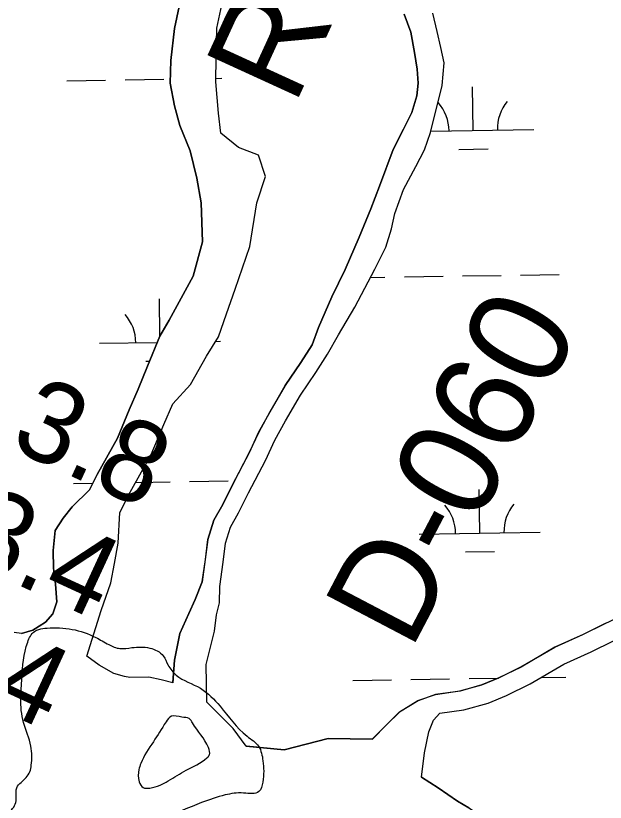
# Model space of a CAD drawing. Extents: x 3855477 to 3893699, y 299188 to 325115.
# Drawn here: x 3867459 to 3867946, y 314439 to 315089 of the extents above; entities that cross this region are included whole.
import ezdxf

# ---------------------------------------------------------------- set-up
doc = ezdxf.new("R2010")
doc.units = 0
for name, color, linetype in [('V-RIVR-EDGE', 7, 'Continuous'), ('V-RIVR-RANG', 7, 'Continuous'), ('V-RIVR-RANG-IDEN', 7, 'Continuous'), ('V-TOPO-SHOR', 7, 'Continuous'), ('V-WETL-SWMP', 7, 'Continuous')]:
    doc.layers.add(name, color=color, linetype=linetype)

msp = doc.modelspace()

# ---------------------------------------------------------------- linework, layer by layer
at = {"layer": 'V-RIVR-EDGE'}
for points in [[(3862579.14, 316706.58), (3862618.94, 316682.57), (3862652.77, 316666.14), (3862683.04, 316656.5), (3862696.18, 316652.88), (3862701.35, 316646.89), (3862715.28, 316640.08), (3862730.01, 316634.47), (3862738.78, 316633.65), (3862748.32, 316626.05), (3862763.45, 316620.43), (3862771.01, 316614.84), (3862792.51, 316606.02), (3862806.84, 316598.81), (3862817.99, 316594.4), (3862834.31, 316586.78), (3862853.02, 316578.37), (3862861.77, 316570.77), (3862880.08, 316564.75), (3862890.05, 316564.73), (3862900.01, 316564.3), (3862907.58, 316561.49), (3862923.9, 316554.68), (3862944.6, 316544.66), (3862975.64, 316529.04), (3863008.68, 316511.03), (3863036.93, 316493.42), (3863051.26, 316484.22), (3863059.61, 316479.82), (3863073.14, 316469.42), (3863078.7, 316461.84), (3863091.04, 316455.43), (3863113.73, 316446.6), (3863137.23, 316440.57), (3863166.3, 316430.53), (3863183.42, 316425.71), (3863207.7, 316412.1), (3863228, 316399.69), (3863238.35, 316395.68), (3863252.68, 316390.47), (3863259.44, 316385.27), (3863266.6, 316378.08), (3863269.37, 316370.9), (3863279.32, 316363.3), (3863294.44, 316355.69), (3863309.17, 316346.89), (3863343, 316331.26), (3863355.34, 316322.06), (3863380.4, 316304.47), (3863423.37, 316277.26), (3863452.02, 316258.46), (3863472.72, 316247.65), (3863532.42, 316214.82), (3863576.2, 316192.79), (3863612.02, 316173.97), (3863662.97, 316147.94), (3863701.98, 316129.91), (3863762.09, 316101.46), (3863803.49, 316080.64), (3863847.67, 316056.62), (3863876.33, 316044.19), (3863896.63, 316031.79), (3863917.72, 316020.58), (3863971.85, 315991.35), (3864020.81, 315966.12), (3864054.23, 315946.51), (3864091.65, 315926.89), (3864114.73, 315913.68), (3864131.85, 315906.86), (3864146.97, 315897.66), (3864174.04, 315883.64), (3864183.18, 315874.06), (3864194.33, 315870.44), (3864207.47, 315866.82), (3864224.19, 315858.81), (3864239.32, 315850.4), (3864262.4, 315839.98), (3864273.56, 315837.17), (3864288.68, 315830.35), (3864303.82, 315827.93), (3864315.37, 315825.11), (3864338.47, 315817.08), (3864360.77, 315810.65), (3864391.41, 315792.24), (3864418.87, 315776.23), (3864435.97, 315762.24), (3864459.04, 315741.86), (3864510.37, 315709.85), (3864535.44, 315695.84), (3864548.97, 315685.44), (3864561.3, 315675.85), (3864568.85, 315666.66), (3864582.37, 315656.66), (3864595.1, 315647.07), (3864600.67, 315641.08), (3864607.02, 315633.09), (3864612.59, 315626.3), (3864620.15, 315622.69), (3864637.27, 315615.88), (3864659.57, 315609.05), (3864678.28, 315601.03), (3864697.4, 315595.4), (3864745.56, 315571.77), (3864769.85, 315563.74), (3864787.37, 315555.73), (3864811.24, 315540.52), (3864821.2, 315537.71), (3864833.16, 315537.68), (3864842.32, 315536.46), (3864849.48, 315531.26), (3864857.43, 315522.87), (3864872.16, 315516.86), (3864908, 315506.01), (3864925.13, 315500.39), (3864937.87, 315498.76), (3864948.62, 315491.56), (3864956.98, 315489.55), (3864964.15, 315487.54), (3865017.51, 315468.28), (3865068.47, 315449.82), (3865096.34, 315439.39), (3865128.59, 315424.96), (3865154.87, 315414.93), (3865175.96, 315401.73), (3865212.19, 315385.7), (3865243.63, 315368.48), (3865263.13, 315356.48), (3865277.85, 315348.07), (3865296.96, 315338.06), (3865316.47, 315331.24), (3865337.16, 315318.04), (3865369.39, 315298.43), (3865405.2, 315275.22), (3865431.87, 315259.61), (3865448.19, 315254), (3865473.66, 315238.39), (3865499.13, 315224.78), (3865515.06, 315217.96), (3865531.77, 315209.15), (3865549.68, 315199.54), (3865571.18, 315191.52), (3865609, 315173.09), (3865653.97, 315145.48), (3865693.76, 315123.07), (3865732.77, 315101.85), (3865776.94, 315077.43), (3865798.43, 315063.82), (3865826.69, 315046.62), (3865853.35, 315032.6), (3865883.2, 315017.39), (3865895.15, 315011.38), (3865904.29, 315003.78), (3865913.04, 314994.59), (3865919.8, 314990.19), (3865927.77, 314987.38), (3865939.71, 314983.37), (3865950.47, 314980.55), (3865961.62, 314976.54), (3865977.53, 314967.34), (3866028.88, 314942.9), (3866056.75, 314928.48), (3866076.64, 314915.28), (3866096.53, 314901.68), (3866120.41, 314888.47), (3866143.9, 314878.05), (3866161.41, 314867.25), (3866178.14, 314862.82), (3866201.24, 314856.79), (3866223.14, 314850.36), (3866245.83, 314837.55), (3866263.73, 314827.14), (3866282.84, 314818.72), (3866292.41, 314818.7), (3866300.78, 314818.28), (3866309.94, 314816.27), (3866326.66, 314808.65), (3866348.53, 314791.06), (3866360.08, 314786.25), (3866377.59, 314778.64), (3866387.55, 314775.02), (3866394.31, 314767.44), (3866401.87, 314762.24), (3866413.81, 314757.03), (3866423.36, 314751.42), (3866432.12, 314749.81), (3866437.69, 314746.21), (3866445.65, 314739.41), (3866454.4, 314732.22), (3866485.45, 314718.99), (3866510.53, 314708.56), (3866533.21, 314691.37), (3866541.97, 314691.35), (3866549.94, 314690.93), (3866556.31, 314686.53), (3866561.87, 314678.55), (3866573.8, 314670.15), (3866598.9, 314663.71), (3866631.14, 314649.28), (3866660.61, 314640.44), (3866694.86, 314628.4), (3866748.2, 314604.36), (3866780.45, 314591.52), (3866811.1, 314575.51), (3866846.93, 314561.47), (3866895.5, 314539.03), (3866932.13, 314524.59), (3866954.81, 314513.38), (3866988.26, 314500.54), (3867018.51, 314486.52), (3867041.2, 314475.3), (3867068.66, 314458.5), (3867097.31, 314440.09), (3867123.99, 314432.46), (3867147.11, 314433.2), (3867169.41, 314427.96), (3867197.28, 314417.13), (3867215.2, 314410.71), (3867238.69, 314401.49), (3867251.43, 314396.27), (3867258.61, 314395.86), (3867271.36, 314397.42), (3867288.1, 314397.78), (3867302.45, 314396.15), (3867345.46, 314385.28), (3867427.5, 314359.57), (3867438.25, 314357.95), (3867445.03, 314357.93), (3867453.42, 314369.47), (3867458.24, 314381.41), (3867462.26, 314395.75), (3867462.28, 314404.12), (3867460.7, 314411.7), (3867457.12, 314414.1), (3867450.75, 314416.11), (3867442.78, 314416.52), (3867438.8, 314420.12), (3867443.19, 314422.1), (3867451.58, 314428.06), (3867458.77, 314437.21), (3867459.58, 314442.79), (3867460, 314450.75), (3867463.6, 314455.13), (3867470.8, 314463.88), (3867472, 314469.46), (3867472.42, 314477.03), (3867471.64, 314485), (3867465.71, 314504.54), (3867463.75, 314514.51), (3867463.37, 314524.48), (3867464.21, 314541.21), (3867469.07, 314571.09), (3867474.67, 314579.84), (3867478.26, 314581.43), (3867485.04, 314582.61), (3867525.27, 314574.94), (3867536.02, 314568.93), (3867545.17, 314565.72), (3867555.14, 314566.49), (3867569.88, 314566.06), (3867581.03, 314559.65), (3867584.99, 314552.07), (3867591.75, 314543.69), (3867611.65, 314532.88), (3867627.95, 314518.09), (3867650.21, 314493.33), (3867659.75, 314484.93), (3867663.31, 314472.97), (3867663.27, 314455.43), (3867660.06, 314447.47), (3867647.3, 314446.31), (3867632.15, 314444.75), (3867612.61, 314438.42), (3867582.29, 314425.34)], [(3867585.16, 314456.42), (3867599.92, 314465.15), (3867617.09, 314475.47), (3867619.08, 314477.86), (3867618.3, 314483.84), (3867605.2, 314504.2), (3867602.42, 314507.79), (3867596.45, 314509), (3867587.68, 314509.82), (3867583.28, 314505.05), (3867572.88, 314488.74), (3867562.48, 314470.83), (3867560.87, 314465.65), (3867561.24, 314455.69), (3867564.42, 314450.9), (3867570, 314450.48)], [(3867570, 314450.48), (3867578.37, 314452.85), (3867585.16, 314456.42)]]:
    msp.add_spline(points, degree=3, dxfattribs=at)
at = {"layer": 'V-TOPO-SHOR'}
msp.add_line((3867649.66, 314484.92), (3867649.61, 314485.09), dxfattribs=at)
for points in [[(3867605.83, 314873.42), (3867613.29, 314901.62), (3867612.43, 314933.89), (3867608.66, 314954.23), (3867603.32, 314976.99), (3867594.77, 314997.79), (3867590.16, 315014.16), (3867586.77, 315032.91), (3867587.36, 315051.62), (3867590.42, 315077.87), (3867594.19, 315096.16)], [(3867640.45, 314862.72), (3867652.58, 314898), (3867658.31, 314934.07), (3867665.58, 314955.77), (3867659.53, 314973.22), (3867643.27, 314979.76), (3867628.43, 314991.6), (3867626.6, 315008.05), (3867624.45, 315033.96), (3867624.57, 315053.94), (3867625.38, 315078.35), (3867629.32, 315097.43)], [(3867731.38, 314878.74), (3867742.79, 314905.66), (3867752.57, 314929.01), (3867759.52, 314947.62), (3867770.97, 314978.11), (3867779.48, 314994.72), (3867786.39, 315008.56), (3867790.5, 315022.43), (3867791.41, 315032.76), (3867790.73, 315044.29), (3867788.49, 315058.23), (3867785.48, 315074.96), (3867780.07, 315089.72)], [(3867755.62, 314879.19), (3867764.95, 314897.38), (3867769.48, 314912.43), (3867772.39, 314925.13), (3867779.35, 314944.93), (3867789.49, 314963.91), (3867796.79, 314977.74), (3867801.7, 314992), (3867811.25, 315030.86), (3867813.03, 315049.53), (3867810.38, 315062.28), (3867807.33, 315075.42), (3867803.51, 315090.57)], [(3867588.83, 314537.52), (3867590.21, 314556.19), (3867594.82, 314578.05), (3867602.16, 314594.7), (3867607.46, 314606.19), (3867613.18, 314620.86), (3867615.76, 314639.16), (3867617.93, 314655.86), (3867622.87, 314671.74), (3867630.17, 314684.81), (3867638.3, 314701.05), (3867652.12, 314727.59), (3867659.86, 314744.63), (3867669.19, 314761.26), (3867681.76, 314783.03), (3867694.7, 314802.02), (3867704.01, 314816.65), (3867709.33, 314830.93), (3867720.35, 314856.31), (3867731.38, 314878.74)], [(3867616.93, 314521.27), (3867616.45, 314552.39), (3867623.41, 314580.1), (3867624.88, 314593.69), (3867627.5, 314603.51), (3867627.62, 314617.09), (3867630.45, 314637.17), (3867632.46, 314652.68), (3867636.56, 314665.86), (3867643.27, 314677.87), (3867651.5, 314694.31), (3867665.44, 314721.1), (3867673.09, 314737.93), (3867682.07, 314753.93), (3867694.31, 314775.15), (3867707.08, 314793.86), (3867716.71, 314809.01), (3867725.75, 314824.9), (3867739.27, 314847.89), (3867755.62, 314879.19)], [(3867463.8, 314578.21), (3867473.38, 314580.89), (3867483.81, 314587.56), (3867489.85, 314594.26), (3867493.14, 314604.19), (3867492.1, 314618.93), (3867490.24, 314632.09), (3867489.99, 314646.83), (3867491.76, 314663.14), (3867498.23, 314673.42), (3867505.9, 314682.91), (3867519.98, 314696.7), (3867526.48, 314709.37), (3867543.12, 314739.47), (3867552.92, 314762.86), (3867560.26, 314779.91), (3867568.02, 314798.95), (3867578.24, 314823.93), (3867585.94, 314836.99), (3867595.69, 314855.21), (3867605.83, 314873.42)], [(3867517.77, 314559.33), (3867529.6, 314597.02), (3867537.62, 314620.04), (3867540.7, 314635.91), (3867543.75, 314652.78), (3867545.24, 314678.09), (3867553.81, 314694.81), (3867571.03, 314725.95), (3867581.42, 314750.75), (3867588.82, 314767.94), (3867603.43, 314783.98), (3867616.78, 314807.23), (3867626.5, 314823.27), (3867633.24, 314842.25), (3867640.45, 314862.72)], [(3867753.62, 314490.88), (3867765.29, 314502.7), (3867776.14, 314513.33), (3867791.36, 314522.73), (3867805.75, 314527.75), (3867826.07, 314530.73), (3867844.03, 314535.72), (3867858.03, 314541.54), (3867876.43, 314550.5), (3867904.46, 314566.93), (3867927.65, 314577.44), (3867946.05, 314586.4), (3867963.65, 314594.58)], [(3867794.18, 314459.57), (3867796.72, 314479.65), (3867800.32, 314496.97), (3867804.21, 314506.59), (3867809.56, 314512.2), (3867829.37, 314515.09), (3867849.25, 314520.62), (3867864.59, 314527), (3867883.96, 314536.44), (3867911.8, 314552.75), (3867934.43, 314563.01), (3867952.9, 314572)], [(3867649.61, 314485.09), (3867680.74, 314482.06), (3867717.14, 314491.51), (3867753.62, 314490.88)], [(3867794.18, 314459.57), (3867808.09, 314450.51), (3867823.99, 314439.59), (3867833.43, 314434.08), (3867885.45, 314400.13), (3867909.77, 314377.5), (3867936.35, 314349.86), (3867965.26, 314327.85), (3867996.17, 314316.28), (3868037.7, 314316.65), (3868074.54, 314324.41), (3868095.25, 314328.88), (3868116.33, 314336.4), (3868151.13, 314348.15), (3868181.33, 314379.86), (3868213.02, 314391.57), (3868247.12, 314403.79), (3868264.17, 314428.29), (3868303.38, 314466.61), (3868319.83, 314479.51)]]:
    msp.add_lwpolyline(points, dxfattribs=at)
at = {"layer": 'V-WETL-SWMP'}
for p, q in [((3867501.41, 315034.74), (3867533.41, 315035.26)), ((3867549.41, 315035.52), (3867581.4, 315036.04)), ((3867624.46, 315036.77), (3867629.32, 315036.85)), ((3867837, 314993.75), (3867836.41, 315029.75)), ((3867802, 314993.18), (3867886.99, 314994.57)), ((3867825.25, 314978.13), (3867849.25, 314978.52)), ((3867752.01, 314872.28), (3867764.12, 314872.48)), ((3867780.12, 314872.74), (3867812.12, 314873.26)), ((3867828.11, 314873.52), (3867860.11, 314874.04)), ((3867876.11, 314874.3), (3867908.1, 314874.82)), ((3867578.27, 314823.97), (3867577.77, 314854.71)), ((3867624.22, 314819.5), (3867628.26, 314819.57)), ((3867528.36, 314817.91), (3867576.1, 314818.68)), ((3867566.6, 314803.1), (3867569.74, 314803.15)), ((3867506.83, 314702.11), (3867522.89, 314702.37)), ((3867558.33, 314702.98), (3867586.74, 314703.44)), ((3867602.74, 314703.7), (3867634.74, 314704.22)), ((3867842.42, 314661.12), (3867841.83, 314697.12)), ((3867792.43, 314660.31), (3867892.41, 314661.94)), ((3867830.67, 314645.5), (3867854.67, 314645.89)), ((3867737.55, 314539.33), (3867769.54, 314539.85)), ((3867785.54, 314540.11), (3867817.53, 314540.63)), ((3867833.53, 314540.89), (3867857.76, 314541.28)), ((3867893.21, 314541.86), (3867913.5, 314542.19))]:
    msp.add_line(p, q, dxfattribs=at)
for points in [[(3867594.19, 315096.15), (3867590.42, 315077.87), (3867587.36, 315051.62), (3867586.77, 315032.91), (3867590.16, 315014.16), (3867594.77, 314997.79), (3867603.32, 314976.99), (3867608.66, 314954.23), (3867612.43, 314933.89), (3867613.29, 314901.62), (3867605.83, 314873.42), (3867595.69, 314855.21), (3867585.94, 314836.99), (3867578.24, 314823.93), (3867568.03, 314798.95), (3867560.26, 314779.91), (3867552.92, 314762.86), (3867543.12, 314739.47), (3867526.48, 314709.37), (3867519.98, 314696.7), (3867505.9, 314682.91), (3867498.23, 314673.43), (3867491.76, 314663.14), (3867490, 314646.83), (3867490.24, 314632.09), (3867492.1, 314618.93), (3867493.14, 314604.19), (3867489.85, 314594.26), (3867483.81, 314587.56), (3867473.38, 314580.9), (3867463.8, 314578.21), (3867457.83, 314579.06)], [(3867517.77, 314559.33), (3867529.6, 314597.02), (3867537.62, 314620.04), (3867540.7, 314635.91), (3867543.75, 314652.78), (3867545.24, 314678.09), (3867553.81, 314694.81), (3867571.03, 314725.95), (3867581.42, 314750.75), (3867588.82, 314767.94), (3867603.43, 314783.98), (3867616.78, 314807.23), (3867626.5, 314823.27), (3867633.24, 314842.25), (3867640.45, 314862.72), (3867652.58, 314898), (3867658.31, 314934.08), (3867665.58, 314955.77), (3867659.53, 314973.22), (3867643.27, 314979.76), (3867628.43, 314991.6), (3867626.6, 315008.05), (3867624.45, 315033.96), (3867624.57, 315053.94), (3867625.38, 315078.35), (3867629.32, 315097.43)], [(3867649.68, 314484.97), (3867649.61, 314485.09), (3867638.61, 314499.54), (3867626.79, 314511.61), (3867616.93, 314521.27), (3867616.45, 314552.39), (3867623.41, 314580.1), (3867624.88, 314593.69), (3867627.5, 314603.51), (3867627.62, 314617.09), (3867630.45, 314637.17), (3867632.46, 314652.68), (3867636.56, 314665.86), (3867643.27, 314677.87), (3867651.5, 314694.31), (3867665.45, 314721.1), (3867673.09, 314737.93), (3867682.07, 314753.93), (3867694.32, 314775.15), (3867707.08, 314793.86), (3867716.71, 314809.01), (3867725.75, 314824.9), (3867739.27, 314847.89), (3867755.62, 314879.19), (3867764.95, 314897.38), (3867769.48, 314912.44), (3867772.39, 314925.13), (3867779.35, 314944.93), (3867789.49, 314963.91), (3867796.79, 314977.74), (3867801.7, 314992), (3867811.25, 315030.86), (3867813.03, 315049.53), (3867810.38, 315062.27), (3867807.33, 315075.42), (3867803.52, 315090.57)], [(3867780.07, 315089.72), (3867785.48, 315074.96), (3867788.49, 315058.23), (3867790.73, 315044.29), (3867791.41, 315032.76), (3867790.5, 315022.43), (3867786.39, 315008.56), (3867779.48, 314994.72), (3867770.96, 314978.11), (3867759.52, 314947.62)], [(3867759.52, 314947.62), (3867752.57, 314929.01), (3867742.79, 314905.66), (3867731.38, 314878.74), (3867720.3, 314856.29), (3867709.29, 314830.91), (3867703.96, 314816.63), (3867694.65, 314801.99), (3867681.71, 314783.01), (3867669.14, 314761.24), (3867659.81, 314744.61), (3867652.07, 314727.57), (3867638.25, 314701.03), (3867630.12, 314684.78), (3867622.82, 314671.72), (3867617.88, 314655.84), (3867615.71, 314639.14), (3867613.14, 314620.84), (3867607.41, 314606.17), (3867602.11, 314594.67), (3867594.77, 314578.02), (3867590.17, 314556.17), (3867588.78, 314537.5), (3867579.29, 314539.98), (3867568.96, 314542.08), (3867553.43, 314541.84), (3867549.05, 314542.68), (3867540.32, 314545.16), (3867528.04, 314552.05), (3867517.77, 314559.33)], [(3867946.11, 314586.28), (3867927.71, 314577.32), (3867904.52, 314566.81), (3867876.49, 314550.39), (3867858.09, 314541.42), (3867844.1, 314535.6), (3867826.14, 314530.61), (3867805.81, 314527.63), (3867791.43, 314522.61), (3867776.21, 314513.21), (3867765.35, 314502.58), (3867753.69, 314490.76), (3867717.21, 314491.39), (3867680.8, 314481.94), (3867649.68, 314484.97)], [(3867833.43, 314434.08), (3867823.99, 314439.59), (3867808.09, 314450.51), (3867794.18, 314459.57), (3867796.72, 314479.65), (3867800.32, 314496.97), (3867804.21, 314506.59), (3867809.56, 314512.2), (3867829.37, 314515.1), (3867849.25, 314520.62), (3867864.59, 314527), (3867883.96, 314536.44), (3867911.8, 314552.75), (3867934.43, 314563.01), (3867952.9, 314572.01)]]:
    msp.add_lwpolyline(points, dxfattribs=at)
for centre, start, end in [((3867781.76, 314993.33), 0.16154, 41.7052), ((3867892.23, 314995.13), 140.16154, 181.7052), ((3867523.11, 314818.29), 0.16154, 41.7052), ((3867787.18, 314660.7), 0.16154, 41.7052), ((3867897.65, 314662.5), 140.16154, 181.7052)]:
    msp.add_arc(centre, 35.25, start, end, dxfattribs=at)

# ---------------------------------------------------------------- texts
at = {"layer": 'V-RIVR-RANG'}
for s, p in [('3.8', (3867452.6, 314732.25)), ('3.4', (3867410.96, 314641.33)), ('3.4', (3867369.32, 314550.41))]:
    msp.add_text(s, height=67, rotation=335.24833, dxfattribs=at).set_placement(p)
at = {"layer": 'V-RIVR-RANG-IDEN'}
for s, rotation, p in [('R-22.8', 65.39313, (3867689.23, 315013.11)), ('D-060', 62.29733, (3867785.2, 314562.98))]:
    msp.add_text(s, height=83, rotation=rotation, dxfattribs=at).set_placement(p)

doc.saveas('drawing.dxf')
